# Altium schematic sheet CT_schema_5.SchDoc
size 366 x 245 mm
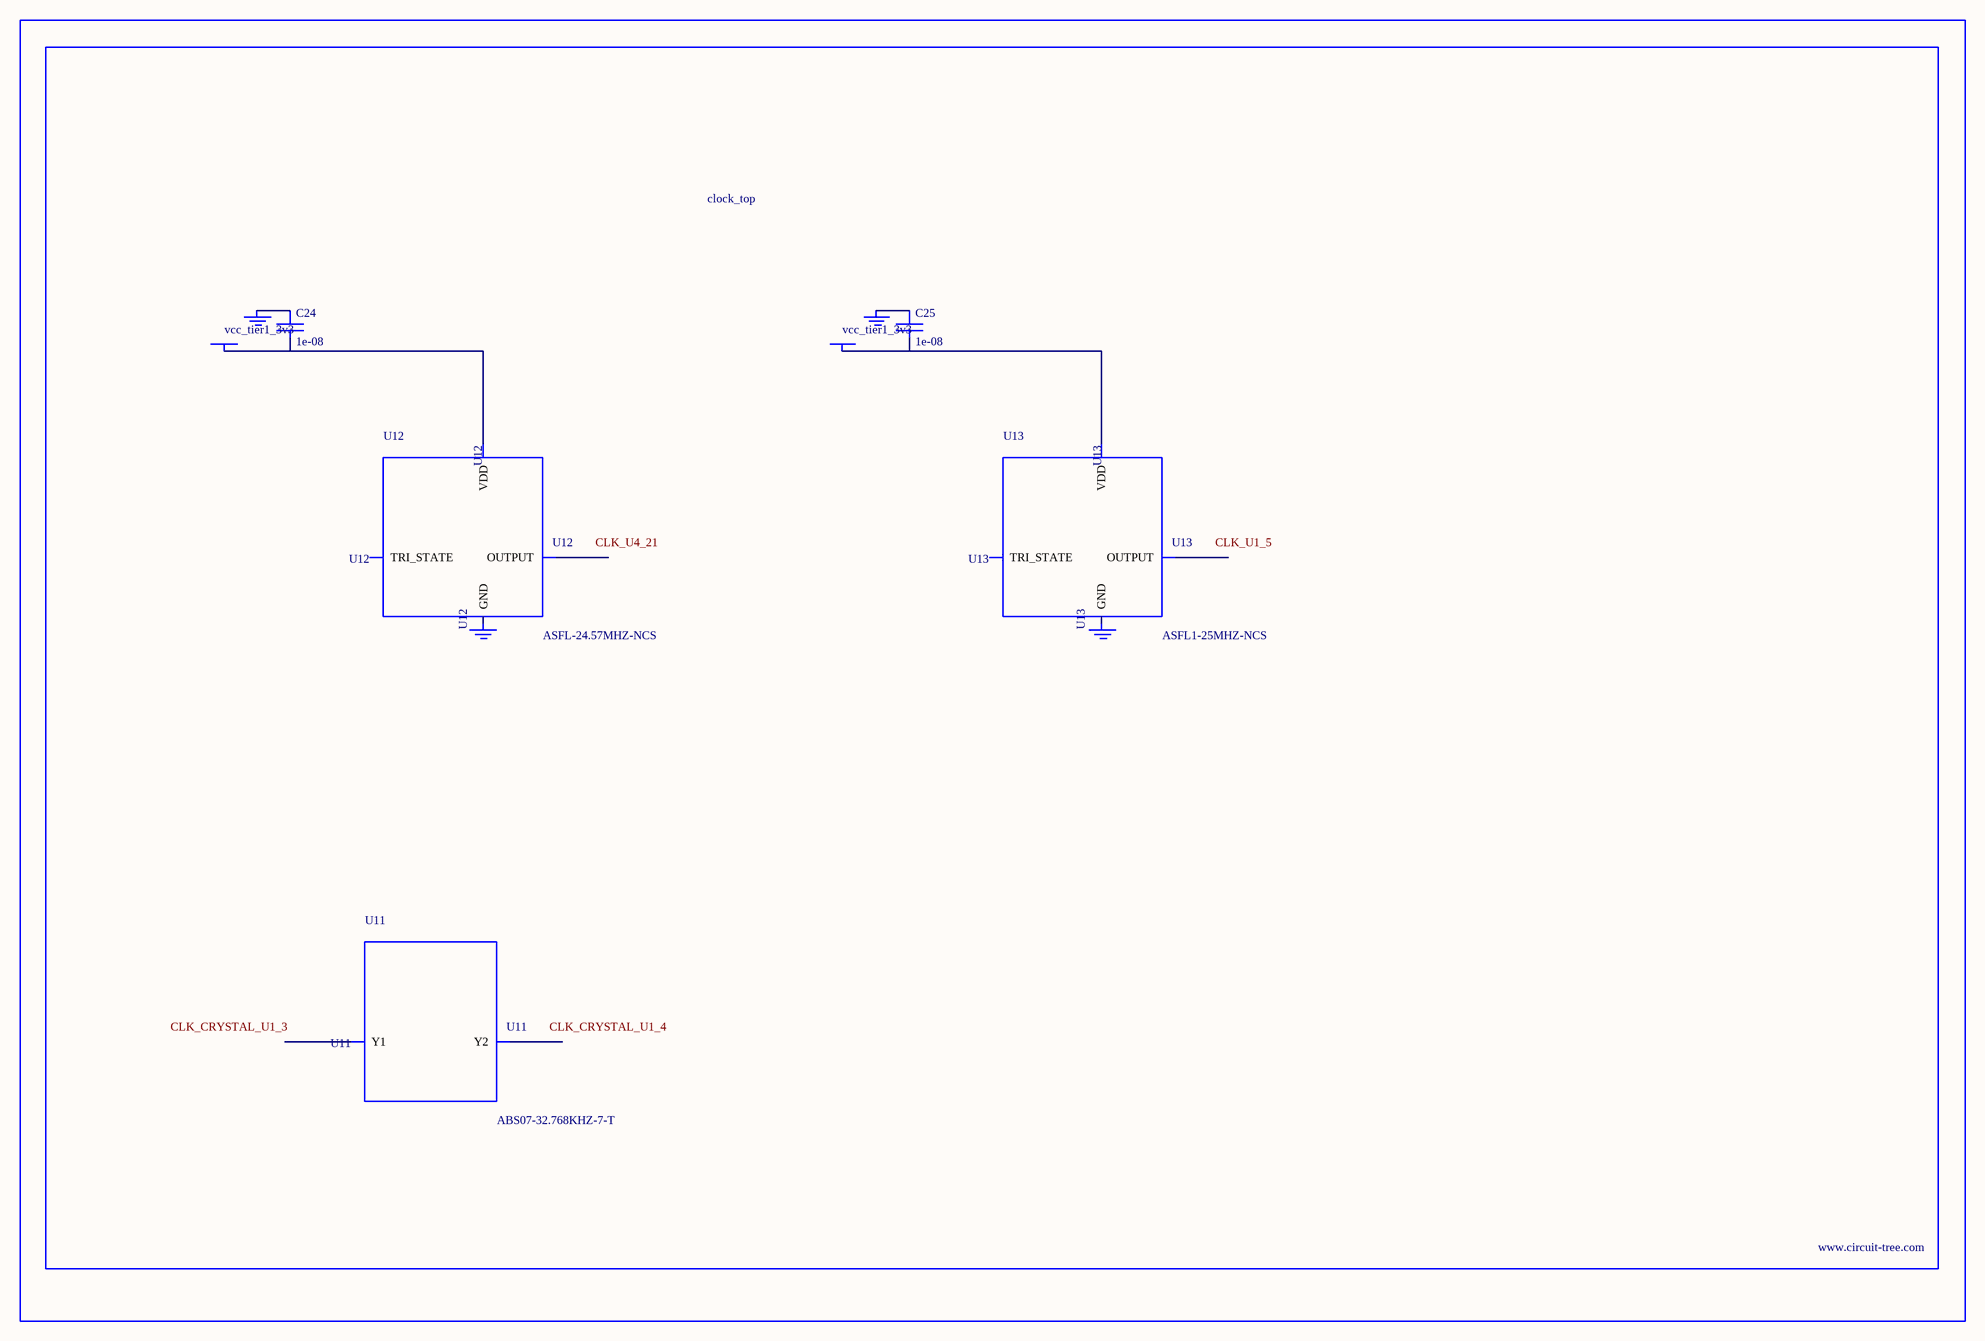
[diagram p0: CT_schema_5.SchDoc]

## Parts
BORDER4  (no value)
C24  1e-08  [C0402]
C25  1e-08  [C0402]
GND_INSTANCE_4_0  (no value)
GND_INSTANCE_4_1  (no value)
GND_INSTANCE_4_2  (no value)
GND_INSTANCE_4_3  (no value)
POWER_INSTANCE_4_0  vcc_tier1_3v3
POWER_INSTANCE_4_1  vcc_tier1_3v3
U11  ABS07-32.768KHZ-7-T  [ABS07-32.768KHZ-7-T]
U12  ASFL-24.57MHZ-NCS  [ASFL1]
U13  ASFL1-25MHZ-NCS  [ASFL1]

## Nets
NetC24_1: C24.1 GND_INSTANCE_4_0.0(GND)
NetC24_2: C24.2 POWER_INSTANCE_4_0.0(PWR) U12.4(VDD)
NetC25_1: C25.1 GND_INSTANCE_4_2.0(GND)
NetC25_2: C25.2 POWER_INSTANCE_4_1.0(PWR) U13.4(VDD)

Not connected (* = marked no-connect by the designer): GND_INSTANCE_4_1 0(GND); GND_INSTANCE_4_3 0(GND); U11 1(Y1) 2(Y2); U12 1(TRI_STATE) 2(GND) 3(OUTPUT); U13 1(TRI_STATE) 2(GND) 3(OUTPUT)

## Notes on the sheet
- Labels drawn without touching a wire or pin: CLK_CRYSTAL_U1_3, CLK_CRYSTAL_U1_4, CLK_U1_5, CLK_U4_21

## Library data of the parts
BORDER4 = BORDER_PAGE4
C24 C25 = C0402C103K3RAC
GND_INSTANCE_4_0-GND_INSTANCE_4_3 = GND
POWER_INSTANCE_4_0 POWER_INSTANCE_4_1 = PWR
